Omron CX-Programmer project 新工程 (CX-Programmer 4.01)

# PLC 新PLC1: CPM2* 

## Program 新程序1 (no task)

### Section 段1

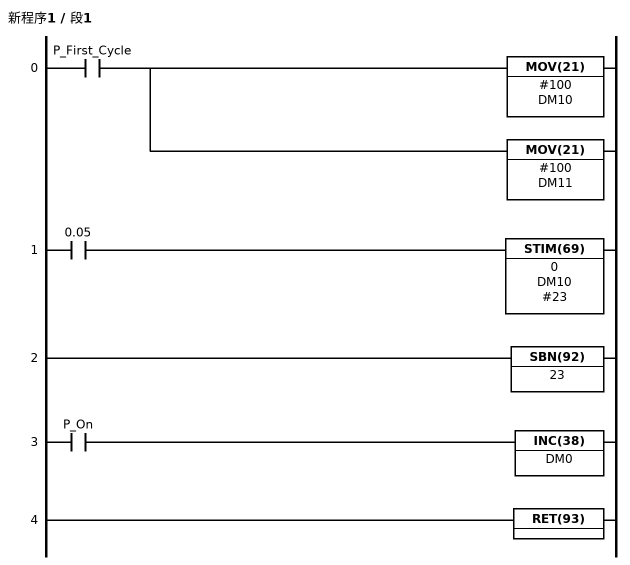
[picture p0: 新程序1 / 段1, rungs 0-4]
; rung 0
LD P_First_Cycle
MOV(21) #100 DM10
MOV(21) #100 DM11
; rung 1
LD 0.05
STIM(69) 0 DM10 #23
; rung 2
SBN(92) 23
; rung 3
LD P_On
INC(38) DM0
; rung 4
RET(93)

### Section END
; rung 0
END(01)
